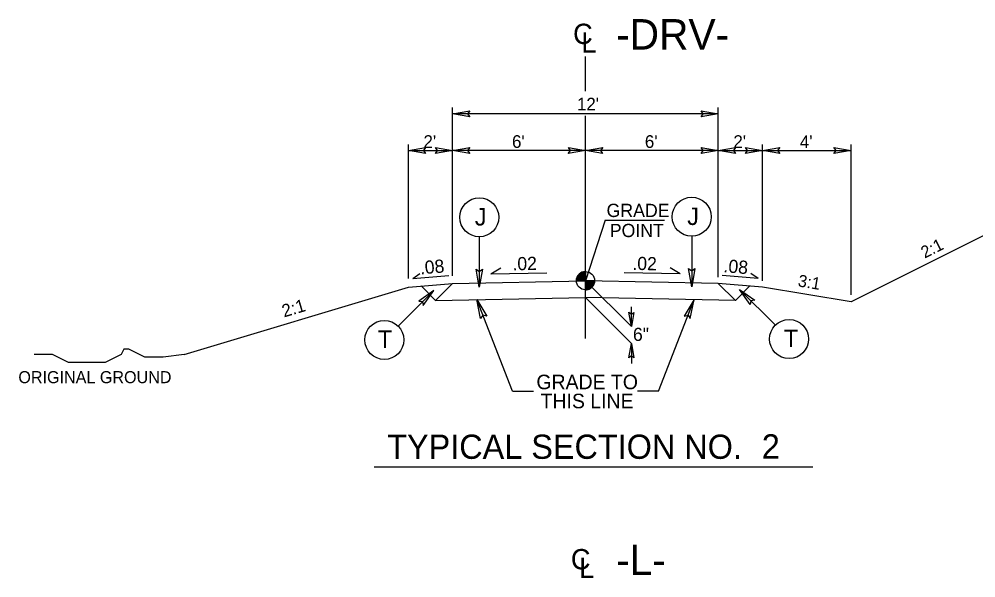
# Model space of a CAD drawing. Extents: x 693533 to 693723, y 486383 to 486493.
# Drawn here: x 693590.27 to 693637.39, y 486409.99 to 486437.52 of the extents above; entities that cross this region are included whole.
import ezdxf

# ---------------------------------------------------------------- set-up
doc = ezdxf.new("R2010")
doc.units = 0
for name, color, linetype in [('Default', 7, 'Continuous'), ('Old_Level_28', 7, 'Continuous'), ('Prop Dimension', 7, 'Continuous'), ('Typical Grade Point Symbol CELL', 7, 'Continuous'), ('Typical Hinge Slope Arterial CELL', 7, 'Continuous'), ('Typical ID Circle CELL', 7, 'Continuous'), ('Typical Pavement Slope CELL', 7, 'Continuous'), ('Typical Pavement Slope Information CELL', 7, 'Continuous'), ('Typical Shoulder Slope CELL', 7, 'Continuous'), ('Typical Shoulder Slope Information CELL', 7, 'Continuous'), ('Typical Slope Point Local CELL', 7, 'Continuous'), ('Typical Terminator CELL', 7, 'Continuous'), ('Typical Text Centerline CELL', 7, 'Continuous'), ('Typical Text General CELL', 7, 'Continuous'), ('Typical Text Grade Point CELL', 7, 'Continuous'), ('Typical Text ID Circle CELL', 7, 'Continuous'), ('Typical Text Label CELL', 7, 'Continuous')]:
    doc.layers.add(name, color=color, linetype=linetype)

msp = doc.modelspace()

# ---------------------------------------------------------------- linework, layer by layer
at = {"layer": 'Default'}
for p, q in [((693618.164, 486433.968), (693618.164, 486435.685)), ((693611.621, 486424.873), (693611.621, 486433.17)), ((693624.707, 486432.858), (693611.621, 486432.858)), ((693618.164, 486421.776), (693618.164, 486432.761)), ((693624.707, 486424.813), (693624.707, 486433.17)), ((693609.44, 486424.733), (693609.44, 486431.336)), ((693626.888, 486424.631), (693626.888, 486431.336)), ((693631.25, 486423.94), (693631.25, 486431.336)), ((693609.44, 486431.043), (693611.621, 486431.043)), ((693618.164, 486431.043), (693611.621, 486431.043)), ((693624.707, 486431.043), (693618.164, 486431.043)), ((693624.707, 486431.043), (693626.888, 486431.043))]:
    msp.add_line(p, q, dxfattribs=at)
at = {"layer": 'Old_Level_28'}
for points in [[(693612.465, 486432.713), (693611.621, 486432.858), (693612.469, 486433.008), (693612.361, 486432.858)], [(693623.863, 486433.003), (693624.707, 486432.858), (693623.859, 486432.708), (693623.966, 486432.858)], [(693610.283, 486430.897), (693609.44, 486431.043), (693610.288, 486431.193), (693610.18, 486431.043)], [(693610.777, 486431.188), (693611.621, 486431.043), (693610.772, 486430.893), (693610.88, 486431.043)], [(693612.465, 486430.897), (693611.621, 486431.043), (693612.469, 486431.193), (693612.361, 486431.043)], [(693617.32, 486431.188), (693618.164, 486431.043), (693617.315, 486430.893), (693617.423, 486431.043)], [(693619.008, 486430.897), (693618.164, 486431.043), (693619.012, 486431.193), (693618.904, 486431.043)], [(693623.863, 486431.188), (693624.707, 486431.043), (693623.859, 486430.893), (693623.966, 486431.043)], [(693625.551, 486430.897), (693624.707, 486431.043), (693625.555, 486431.193), (693625.448, 486431.043)], [(693626.044, 486431.188), (693626.888, 486431.043), (693626.04, 486430.893), (693626.147, 486431.043)], [(693627.732, 486430.897), (693626.888, 486431.043), (693627.736, 486431.193), (693627.629, 486431.043)], [(693630.406, 486431.188), (693631.25, 486431.043), (693630.402, 486430.893), (693630.509, 486431.043)]]:
    msp.add_lwpolyline(points, close=True, dxfattribs=at)
at = {"layer": 'Prop Dimension'}
for p, q in [((693626.888, 486431.043), (693631.25, 486431.043)), ((693619.135, 486427.612), (693618.164, 486424.631)), ((693620.429, 486422.367), (693618.164, 486424.631)), ((693620.427, 486421.54), (693618.162, 486423.805)), ((693614.562, 486419.195), (693612.809, 486423.698)), ((693620.429, 486422.367), (693620.429, 486423.336)), ((693621.765, 486419.195), (693623.519, 486423.697)), ((693620.427, 486421.54), (693620.427, 486420.551)), ((693614.562, 486419.195), (693615.599, 486419.195)), ((693621.765, 486419.195), (693620.729, 486419.195))]:
    msp.add_line(p, q, dxfattribs=at)
at = {"layer": 'Typical Grade Point Symbol CELL'}
for p, q in [((693618.164, 486425.079), (693618.164, 486424.631)), ((693618.164, 486424.631), (693617.716, 486424.631)), ((693618.611, 486424.63), (693618.164, 486424.631)), ((693618.164, 486424.184), (693618.164, 486424.631)), ((693618.164, 486424.631), (693618.611, 486424.63))]:
    msp.add_line(p, q, dxfattribs=at)
for points in [[(693617.73, 486424.743), (693618.164, 486424.743)], [(693617.733, 486424.752), (693618.164, 486424.752)], [(693617.735, 486424.761), (693618.164, 486424.761)], [(693617.738, 486424.77), (693618.164, 486424.77)], [(693617.741, 486424.779), (693618.164, 486424.779)], [(693617.744, 486424.788), (693618.164, 486424.788)], [(693617.748, 486424.797), (693618.164, 486424.797)], [(693617.752, 486424.806), (693618.164, 486424.806)], [(693617.756, 486424.814), (693618.164, 486424.814)], [(693617.76, 486424.823), (693618.164, 486424.823)], [(693617.764, 486424.832), (693618.164, 486424.832)], [(693617.769, 486424.841), (693618.164, 486424.841)], [(693617.774, 486424.85), (693618.164, 486424.85)], [(693617.779, 486424.859), (693618.164, 486424.859)], [(693617.784, 486424.868), (693618.164, 486424.868)], [(693617.79, 486424.877), (693618.164, 486424.877)], [(693617.796, 486424.886), (693618.164, 486424.886)], [(693617.803, 486424.895), (693618.164, 486424.895)], [(693617.809, 486424.904), (693618.164, 486424.904)], [(693617.816, 486424.913), (693618.164, 486424.913)], [(693617.824, 486424.922), (693618.164, 486424.922)], [(693617.832, 486424.931), (693618.164, 486424.931)], [(693617.84, 486424.94), (693618.164, 486424.94)], [(693617.849, 486424.949), (693618.164, 486424.949)], [(693617.858, 486424.958), (693618.164, 486424.958)], [(693617.867, 486424.967), (693618.164, 486424.967)], [(693617.878, 486424.976), (693618.164, 486424.976)], [(693617.889, 486424.985), (693618.164, 486424.985)], [(693617.901, 486424.994), (693618.164, 486424.994)], [(693617.914, 486425.002), (693618.164, 486425.002)], [(693617.928, 486425.011), (693618.164, 486425.011)], [(693617.943, 486425.02), (693618.164, 486425.02)], [(693617.959, 486425.029), (693618.164, 486425.029)], [(693617.978, 486425.038), (693618.164, 486425.038)], [(693617.999, 486425.047), (693618.164, 486425.047)], [(693618.024, 486425.056), (693618.164, 486425.056)], [(693618.054, 486425.065), (693618.164, 486425.065)], [(693618.1, 486425.074), (693618.164, 486425.074)], [(693617.716, 486424.644), (693618.164, 486424.644)], [(693617.716, 486424.635), (693617.716, 486424.635), (693618.164, 486424.635)], [(693617.717, 486424.662), (693618.164, 486424.662)], [(693617.717, 486424.653), (693618.164, 486424.653)], [(693617.718, 486424.671), (693618.164, 486424.671)], [(693617.719, 486424.68), (693618.164, 486424.68)], [(693617.72, 486424.689), (693618.164, 486424.689)], [(693617.721, 486424.698), (693618.164, 486424.698)], [(693617.722, 486424.707), (693618.164, 486424.707)], [(693617.724, 486424.716), (693618.164, 486424.716)], [(693617.726, 486424.725), (693618.164, 486424.725)], [(693617.728, 486424.734), (693618.164, 486424.734)], [(693618.164, 486424.624), (693618.611, 486424.624), (693618.611, 486424.624)], [(693618.164, 486424.616), (693618.611, 486424.616)], [(693618.164, 486424.607), (693618.61, 486424.607)], [(693618.164, 486424.598), (693618.61, 486424.598)], [(693618.164, 486424.589), (693618.609, 486424.589)], [(693618.164, 486424.58), (693618.608, 486424.58)], [(693618.164, 486424.571), (693618.607, 486424.571)], [(693618.164, 486424.562), (693618.605, 486424.562)], [(693618.164, 486424.553), (693618.604, 486424.553)], [(693618.164, 486424.544), (693618.602, 486424.544)], [(693618.164, 486424.535), (693618.601, 486424.535)], [(693618.164, 486424.526), (693618.598, 486424.526)], [(693618.164, 486424.517), (693618.596, 486424.517)], [(693618.164, 486424.508), (693618.594, 486424.508)], [(693618.164, 486424.499), (693618.592, 486424.499)], [(693618.164, 486424.49), (693618.589, 486424.49)], [(693618.164, 486424.481), (693618.586, 486424.481)], [(693618.164, 486424.472), (693618.583, 486424.472)], [(693618.164, 486424.463), (693618.579, 486424.463)], [(693618.164, 486424.454), (693618.575, 486424.454)], [(693618.164, 486424.445), (693618.571, 486424.445)], [(693618.164, 486424.437), (693618.567, 486424.437)], [(693618.164, 486424.428), (693618.563, 486424.428)], [(693618.164, 486424.419), (693618.558, 486424.419)], [(693618.164, 486424.41), (693618.553, 486424.41)], [(693618.164, 486424.401), (693618.548, 486424.401)], [(693618.164, 486424.392), (693618.542, 486424.392)], [(693618.164, 486424.383), (693618.536, 486424.383)], [(693618.164, 486424.374), (693618.53, 486424.374)], [(693618.164, 486424.365), (693618.524, 486424.365)], [(693618.164, 486424.356), (693618.517, 486424.356)], [(693618.164, 486424.347), (693618.51, 486424.347)], [(693618.164, 486424.338), (693618.502, 486424.338)], [(693618.164, 486424.329), (693618.494, 486424.329)], [(693618.164, 486424.32), (693618.486, 486424.32)], [(693618.164, 486424.311), (693618.477, 486424.311)], [(693618.164, 486424.302), (693618.467, 486424.302)], [(693618.164, 486424.293), (693618.457, 486424.293)], [(693618.164, 486424.284), (693618.446, 486424.284)], [(693618.164, 486424.275), (693618.435, 486424.275)], [(693618.164, 486424.266), (693618.423, 486424.266)], [(693618.164, 486424.257), (693618.41, 486424.257)], [(693618.164, 486424.249), (693618.397, 486424.249)], [(693618.164, 486424.24), (693618.381, 486424.24)], [(693618.164, 486424.231), (693618.364, 486424.231)], [(693618.164, 486424.222), (693618.345, 486424.222)], [(693618.164, 486424.213), (693618.324, 486424.213)], [(693618.164, 486424.204), (693618.297, 486424.204)], [(693618.164, 486424.195), (693618.265, 486424.195)], [(693618.164, 486424.186), (693618.213, 486424.186)]]:
    msp.add_lwpolyline(points, dxfattribs=at)
msp.add_circle((693618.164, 486424.631), 0.448, dxfattribs=at)
for start, end in [(89.9905, 179.9905), (269.9905, 359.9905)]:
    msp.add_arc((693618.164, 486424.631), 0.448, start, end, dxfattribs=at)
at = {"layer": 'Typical ID Circle CELL'}
for p, q in [((693612.934, 486426.792), (693612.934, 486424.307)), ((693623.397, 486426.82), (693623.397, 486424.334)), ((693608.935, 486422.394), (693610.693, 486424.151)), ((693627.517, 486422.437), (693625.758, 486424.194))]:
    msp.add_line(p, q, dxfattribs=at)
for centre in [(693612.934, 486427.754), (693623.397, 486427.781), (693608.256, 486421.713), (693628.196, 486421.757)]:
    msp.add_circle(centre, 0.962, dxfattribs=at)
at = {"layer": 'Typical Pavement Slope CELL'}
for p, q in [((693611.621, 486424.501), (693618.164, 486424.631)), ((693624.707, 486424.501), (693618.164, 486424.631)), ((693624.707, 486424.501), (693625.551, 486423.657)), ((693626.265, 486424.371), (693625.551, 486423.657)), ((693610.777, 486423.657), (693618.162, 486423.805)), ((693625.551, 486423.657), (693618.162, 486423.805))]:
    msp.add_line(p, q, dxfattribs=at)
at = {"layer": 'Typical Pavement Slope Information CELL'}
for p, q in [((693613.502, 486424.962), (693613.998, 486425.262)), ((693622.826, 486424.962), (693622.33, 486425.262)), ((693609.657, 486424.737), (693610.012, 486424.984)), ((693609.657, 486424.737), (693611.43, 486424.888)), ((693613.502, 486424.962), (693616.266, 486425.018)), ((693622.826, 486424.962), (693620.062, 486425.018)), ((693626.67, 486424.737), (693624.897, 486424.888)), ((693626.67, 486424.737), (693626.316, 486424.984))]:
    msp.add_line(p, q, dxfattribs=at)
at = {"layer": 'Typical Shoulder Slope CELL'}
for p, q in [((693639.65, 486427.792), (693631.25, 486423.592)), ((693609.44, 486424.319), (693611.621, 486424.501)), ((693610.777, 486423.657), (693610.063, 486424.371)), ((693611.621, 486424.501), (693610.777, 486423.657)), ((693626.888, 486424.319), (693624.707, 486424.501)), ((693631.25, 486423.592), (693626.888, 486424.319))]:
    msp.add_line(p, q, dxfattribs=at)
at = {"layer": 'Typical Slope Point Local CELL'}
msp.add_line((693598.402, 486420.992), (693609.44, 486424.319), dxfattribs=at)
msp.add_lwpolyline([(693598.402, 486420.992), (693597.364, 486420.863), (693597.105, 486420.863), (693596.716, 486420.863), (693596.456, 486420.863), (693596.197, 486420.992), (693595.938, 486421.122), (693595.678, 486421.253), (693595.419, 486421.253), (693595.289, 486420.992), (693595.029, 486420.863), (693594.77, 486420.733), (693594.511, 486420.604), (693594.251, 486420.604), (693593.992, 486420.604), (693593.733, 486420.604), (693593.473, 486420.604), (693593.214, 486420.604), (693592.955, 486420.604), (693592.695, 486420.604), (693592.436, 486420.733), (693592.177, 486420.863), (693591.917, 486420.992), (693591.528, 486420.992), (693591.268, 486420.992), (693591.009, 486420.992)], dxfattribs=at)
at = {"layer": 'Typical Terminator CELL'}
for points in [[(693623.55, 486425.225), (693623.397, 486424.334), (693623.239, 486425.23), (693623.397, 486425.116)], [(693613.087, 486425.198), (693612.934, 486424.307), (693612.776, 486425.202), (693612.934, 486425.089)], [(693610.172, 486423.413), (693610.693, 486424.151), (693609.948, 486423.63), (693610.14, 486423.598)], [(693626.28, 486423.456), (693625.758, 486424.194), (693626.504, 486423.673), (693626.311, 486423.641)], [(693612.999, 486422.765), (693612.809, 486423.698), (693613.306, 486422.88), (693613.108, 486422.931)], [(693623.329, 486422.765), (693623.519, 486423.697), (693623.021, 486422.88), (693623.22, 486422.931)], [(693620.55, 486423.07), (693620.429, 486422.367), (693620.304, 486423.074), (693620.429, 486422.984)], [(693620.305, 486420.837), (693620.427, 486421.54), (693620.552, 486420.833), (693620.427, 486420.923)]]:
    msp.add_lwpolyline(points, close=True, dxfattribs=at)
at = {"layer": 'Typical Text Grade Point CELL'}
msp.add_line((693619.135, 486427.612), (693622.056, 486427.612), dxfattribs=at)
at = {"layer": 'Typical Text Label CELL'}
msp.add_line((693607.757, 486415.453), (693629.362, 486415.453), dxfattribs=at)

# ---------------------------------------------------------------- texts
at = {"layer": 'Default'}
for s, p in [("12'", (693617.742, 486433.018)), ("2'", (693610.184, 486431.175)), ("6'", (693614.546, 486431.175)), ("6'", (693621.089, 486431.175)), ("2'", (693625.451, 486431.175))]:
    msp.add_text(s, height=0.6249, dxfattribs=at).set_placement(p)
msp.add_text('2:1', height=0.6249, rotation=16.4567, dxfattribs=at).set_placement((693603.314, 486422.817))
at = {"layer": 'Prop Dimension'}
msp.add_text("4'", height=0.6249, dxfattribs=at).set_placement((693628.723, 486431.163))
msp.add_text('6"', height=0.6476, rotation=0, dxfattribs=at).set_placement((693620.504, 486421.664))
at = {"layer": 'Typical Hinge Slope Arterial CELL'}
for s, rotation, p in [('2:1', 26.565, (693634.873, 486425.715)), ('3:1', 350.5377, (693628.6, 486424.356))]:
    msp.add_text(s, height=0.5937, rotation=rotation, dxfattribs=at).set_placement(p)
msp.add_text('ORIGINAL GROUND', height=0.59365, dxfattribs=at).set_placement((693590.229, 486419.581))
at = {"layer": 'Typical Shoulder Slope Information CELL'}
for s, rotation, p in [('.08', 4.8901, (693610.035, 486424.939)), ('.02', 1.1457, (693614.574, 486425.141)), ('.02', 358.8543, (693620.47, 486425.166)), ('.08', 355.1099, (693624.945, 486425.055))]:
    msp.add_text(s, height=0.6476, rotation=rotation, dxfattribs=at).set_placement(p)
at = {"layer": 'Typical Text Centerline CELL'}
for p in [(693617.554, 486436.295), (693617.446, 486410.408)]:
    msp.add_text('C', height=1, dxfattribs=at).set_placement(p)
for p in [(693617.963, 486435.875), (693617.855, 486409.988)]:
    msp.add_text('L', height=1, rotation=359.9469, dxfattribs=at).set_placement(p)
at = {"layer": 'Typical Text General CELL'}
for s, p in [('GRADE TO', (693615.748, 486419.283)), ('THIS LINE', (693615.956, 486418.344))]:
    msp.add_text(s, height=0.7161, dxfattribs=at).set_placement(p)
at = {"layer": 'Typical Text Grade Point CELL'}
for s, p in [('GRADE', (693619.203, 486427.768)), ('POINT', (693619.36, 486426.78))]:
    msp.add_text(s, height=0.6525, dxfattribs=at).set_placement(p)
at = {"layer": 'Typical Text ID Circle CELL'}
for s, p in [('J', (693612.713, 486427.348)), ('J', (693623.176, 486427.375)), ('T', (693607.934, 486421.317)), ('T', (693627.936, 486421.36))]:
    msp.add_text(s, height=0.861, dxfattribs=at).set_placement(p)
at = {"layer": 'Typical Text Label CELL'}
for s, height, p in [('-DRV-', 1.5, (693619.672, 486436.02)), ('TYPICAL SECTION NO.  ', 1.19356, (693608.398, 486415.853)), ('2', 1.194, (693626.85, 486415.869)), ('-L-', 1.5, (693619.672, 486410.124))]:
    msp.add_text(s, height=height, dxfattribs=at).set_placement(p)

doc.saveas('drawing.dxf')
